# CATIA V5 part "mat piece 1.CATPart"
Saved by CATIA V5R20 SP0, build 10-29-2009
Part number: mat piece 1
Publications: "Esquisse.3"
Bounding box of the stored display mesh (mm): x -10 to 10, y 0 to 690, z -9.969 to 9.969
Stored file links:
  G:\Khaled_CFAO_2011\SIL\SIL_GR1\blaboucarri\Khaled\CAD_CATIA\mat piece 1.CATPart
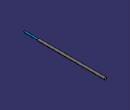
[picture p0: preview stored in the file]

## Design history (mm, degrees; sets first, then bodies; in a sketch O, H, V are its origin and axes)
Body1 (main body)
  Sketch1 on xy-plane, origin (0, 0, 0), H (1, 0, 0), V (0, 1, 0)
    line L1 (0, 0) -> (-6, 0)
    line L2 (-6, 0) -> (-6, 120)
    line L3 (-6, 120) -> (-10, 120)
    line L4 (-10, 120) -> (-10, 690)
    line L5 (-10, 690) -> (0, 690)
    point P5 (0, 690)
    line L6 (0, 690) -> (0, 0)
    length L4 = 570
    length L2 = 120
    length L1 = 6
    length L5 = 10
    horizontal: L1 H, L3 H, L5 H
    vertical: L2 V, L4 V, L6 V
    coincidence: P5 V
  Shaft1: profile Sketch1, axis Sketch1.L6, angle 360
Body2
  Sketch2 on zx-plane, origin (0, 0, 0), H (-1, 0, 0), V (0, 0, 1)
    line L1 (-10, 10) -> (10, 10)
    line L2 (10, 10) -> (10, -10)
    line L3 (10, -10) -> (-10, -10)
    line L4 (-10, -10) -> (-10, 10)
    reference intersected line E1 through (0, 0) direction (-1, 0) from xy-plane
    reference intersected line E2 through (0, 0) direction (-1, 0) from xy-plane
    reference intersected line E3 through (0, 0) direction (0, -1) from yz-plane
    distance L1 E1 = 10
    length L1 = 20
    horizontal: L1 H, L3 H
    vertical: L2 V, L4 V
    symmetry: L1 L3 E2, L2 L4 E3
  Pad1: profile Sketch2, direction (0, 1, 0), length 20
